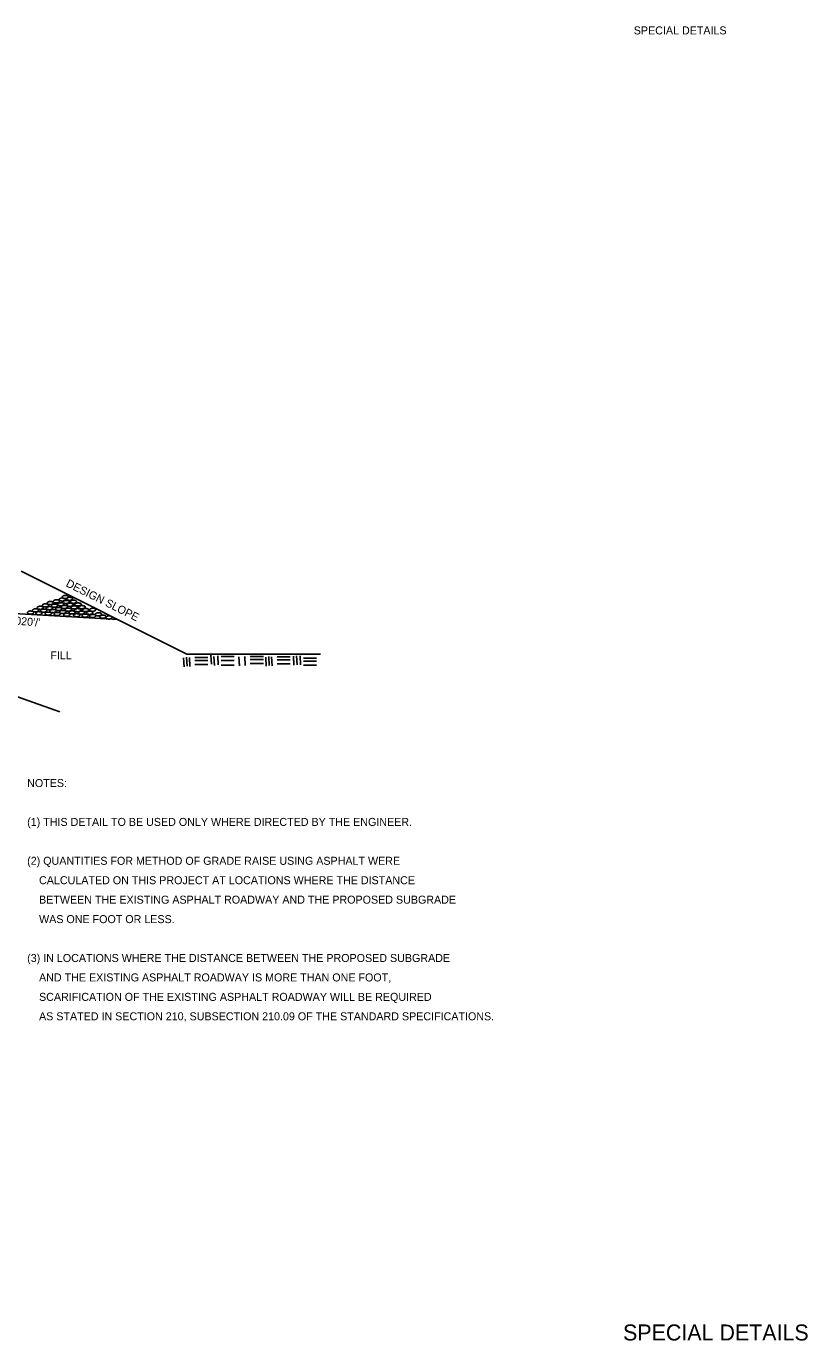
# Model space of a CAD drawing. Extents: x -2842 to 2681, y -2139 to 474.
# Drawn here: x 2096 to 2681, y -512 to 474 of the extents above; entities that cross this region are included whole.
import ezdxf

# ---------------------------------------------------------------- set-up
doc = ezdxf.new("R2010")
doc.units = 0
for name, color, linetype in [('R_Border', 7, 'Continuous'), ('R_Border Prem', 7, 'Continuous'), ('R_Grid', 7, 'Continuous')]:
    doc.layers.add(name, color=color, linetype=linetype)

msp = doc.modelspace()

# ---------------------------------------------------------------- linework, layer by layer
at = {"layer": 'R_Grid'}
for p, q in [((2215.91, 3.06), (2091.72, 65.14)), ((2010.36, 37.94), (2164.16, 28.93)), ((1946.93, 21.56), (2120.76, -40.3)), ((2213.37, 0.4), (2213.76, -6.38)), ((2215.7, 0.85), (2216.09, -5.92)), ((2315.99, 3.06), (2215.91, 3.06)), ((2217.73, 0.63), (2218.1, -6.14)), ((2231.66, 0.63), (2221.87, 0.63)), ((2233.88, 2.35), (2234.23, -4.41)), ((2236.17, 1.2), (2236.54, -5.57)), ((2239.05, 1.79), (2239.43, -4.99)), ((2251.29, 1.21), (2241.46, 1.21)), ((2254.92, 1.13), (2255.31, -5.64)), ((2259.27, 1.37), (2259.65, -5.39)), ((2273.2, 1.37), (2263.42, 1.37)), ((2274.95, 0.83), (2275.34, -5.93)), ((2277.3, 1.31), (2277.65, -5.47)), ((2279.31, 1.07), (2279.69, -5.71)), ((2293.24, 1.07), (2283.46, 1.07)), ((2295.72, 1.55), (2296.09, -5.21)), ((2298.15, 1.81), (2298.52, -4.95)), ((2300.71, 1.81), (2301.09, -4.95)), ((2313, 0.05), (2303.21, 0.05)), ((2231.66, -1.62), (2221.87, -1.62)), ((2231.66, -4.64), (2221.87, -4.64)), ((2251.29, -1.69), (2241.46, -1.69)), ((2251.29, -5.14), (2241.46, -5.14)), ((2273.2, -0.89), (2263.42, -0.89)), ((2273.2, -3.91), (2263.42, -3.91)), ((2293.24, -1.17), (2283.46, -1.17)), ((2293.24, -4.19), (2283.46, -4.19)), ((2313, -2.18), (2303.21, -2.18)), ((2313, -5.22), (2303.21, -5.22))]:
    msp.add_line(p, q, dxfattribs=at)
for points in [[(2109.9, 38.41), (2109.04, 38.49), (2108.06, 38.76), (2107.54, 39.21), (2107.48, 39.51), (2107.71, 40), (2108.04, 40.24), (2108.61, 40.59), (2109.4, 40.74), (2109.79, 40.74), (2110.41, 40.71), (2111.11, 40.64), (2111.64, 40.44), (2112.12, 39.96), (2112.18, 39.68), (2112.03, 39.2), (2111.65, 38.91), (2111.31, 38.72), (2110.78, 38.55), (2110.44, 38.46), (2109.9, 38.41)], [(2113.47, 40.14), (2112.65, 40.23), (2111.65, 40.56), (2111.18, 40.98), (2111.09, 41.28), (2111.35, 41.78), (2111.63, 42.04), (2112.16, 42.32), (2112.94, 42.51), (2113.38, 42.51), (2114, 42.54), (2114.69, 42.4), (2115.25, 42.15), (2115.73, 41.74), (2115.8, 41.42), (2115.68, 40.95), (2115.29, 40.63), (2114.93, 40.51), (2114.33, 40.31), (2114, 40.19), (2113.47, 40.14)], [(2116.69, 38.19), (2115.86, 38.28), (2114.9, 38.55), (2114.39, 39.03), (2114.3, 39.27), (2114.57, 39.83), (2114.87, 40.06), (2115.37, 40.38), (2116.18, 40.56), (2116.6, 40.56), (2117.23, 40.58), (2117.93, 40.47), (2118.46, 40.19), (2118.96, 39.8), (2119.02, 39.47), (2118.89, 39.01), (2118.51, 38.67), (2118.12, 38.51), (2117.56, 38.36), (2117.23, 38.24), (2116.69, 38.19)], [(2118.08, 41.42), (2117.23, 41.51), (2116.24, 41.8), (2115.73, 42.25), (2115.68, 42.56), (2115.93, 43.06), (2116.21, 43.3), (2116.75, 43.58), (2117.56, 43.77), (2117.98, 43.77), (2118.61, 43.74), (2119.31, 43.7), (2119.82, 43.47), (2120.3, 43.02), (2120.38, 42.72), (2120.22, 42.23), (2119.84, 41.95), (2119.48, 41.79), (2118.94, 41.56), (2118.61, 41.43), (2118.08, 41.42)], [(2121.42, 39.22), (2120.57, 39.33), (2119.56, 39.62), (2119.04, 40.06), (2118.98, 40.36), (2119.26, 40.85), (2119.52, 41.1), (2120.13, 41.41), (2120.91, 41.59), (2121.3, 41.59), (2121.93, 41.56), (2122.61, 41.48), (2123.17, 41.28), (2123.62, 40.81), (2123.71, 40.54), (2123.55, 40.04), (2123.19, 39.78), (2122.82, 39.58), (2122.3, 39.4), (2121.96, 39.29), (2121.42, 39.22)], [(2122.47, 42.84), (2121.64, 42.93), (2120.64, 43.2), (2120.16, 43.66), (2120.1, 43.95), (2120.35, 44.44), (2120.62, 44.68), (2121.17, 45), (2121.96, 45.19), (2122.39, 45.19), (2123, 45.13), (2123.71, 45.09), (2124.23, 44.88), (2124.71, 44.42), (2124.79, 44.13), (2124.64, 43.65), (2124.27, 43.37), (2123.9, 43.17), (2123.33, 42.95), (2123, 42.85), (2122.47, 42.84)], [(2124.07, 37.26), (2123.24, 37.35), (2122.27, 37.64), (2121.77, 38.09), (2121.72, 38.38), (2121.96, 38.89), (2122.19, 39.12), (2122.78, 39.4), (2123.56, 39.62), (2123.97, 39.62), (2124.6, 39.58), (2125.3, 39.52), (2125.83, 39.25), (2126.35, 38.84), (2126.41, 38.51), (2126.27, 38.06), (2125.9, 37.76), (2125.52, 37.62), (2124.95, 37.39), (2124.6, 37.27), (2124.07, 37.26)], [(2124.71, 44.7), (2123.88, 44.8), (2122.91, 45.05), (2122.43, 45.55), (2122.35, 45.81), (2122.6, 46.32), (2122.83, 46.55), (2123.41, 46.85), (2124.2, 47.05), (2124.62, 47.05), (2125.25, 47.02), (2125.94, 46.97), (2126.46, 46.7), (2126.99, 46.3), (2127.07, 45.94), (2126.92, 45.52), (2126.54, 45.19), (2126.16, 45.05), (2125.59, 44.84), (2125.25, 44.71), (2124.71, 44.7)], [(2125.42, 40.97), (2124.56, 41.06), (2123.58, 41.32), (2123.07, 41.8), (2123, 42.07), (2123.25, 42.6), (2123.54, 42.81), (2124.09, 43.1), (2124.89, 43.33), (2125.32, 43.33), (2125.94, 43.27), (2126.63, 43.23), (2127.14, 42.95), (2127.64, 42.56), (2127.73, 42.2), (2127.56, 41.78), (2127.18, 41.44), (2126.82, 41.31), (2126.28, 41.1), (2125.94, 40.98), (2125.42, 40.97)], [(2127.88, 43.35), (2127.07, 43.45), (2126.06, 43.69), (2125.57, 44.18), (2125.5, 44.43), (2125.76, 44.97), (2126.04, 45.17), (2126.59, 45.48), (2127.38, 45.7), (2127.78, 45.7), (2128.43, 45.64), (2129.12, 45.6), (2129.66, 45.34), (2130.14, 44.92), (2130.23, 44.58), (2130.06, 44.17), (2129.71, 43.82), (2129.3, 43.66), (2128.76, 43.48), (2128.43, 43.37), (2127.88, 43.35)], [(2128.21, 38.84), (2127.37, 38.96), (2126.38, 39.2), (2125.9, 39.69), (2125.82, 39.95), (2126.07, 40.49), (2126.36, 40.68), (2126.92, 41.01), (2127.71, 41.23), (2128.12, 41.23), (2128.74, 41.16), (2129.44, 41.12), (2129.96, 40.86), (2130.47, 40.45), (2130.54, 40.1), (2130.39, 39.68), (2130, 39.36), (2129.64, 39.17), (2129.08, 39.01), (2128.74, 38.87), (2128.21, 38.84)], [(2130.89, 41.14), (2130.01, 41.23), (2129.05, 41.45), (2128.52, 41.96), (2128.46, 42.22), (2128.72, 42.74), (2129.01, 42.95), (2129.57, 43.28), (2130.37, 43.48), (2130.77, 43.48), (2131.41, 43.45), (2132.09, 43.4), (2132.63, 43.13), (2133.09, 42.72), (2133.18, 42.38), (2133.02, 41.94), (2132.66, 41.62), (2132.28, 41.44), (2131.74, 41.28), (2131.41, 41.16), (2130.89, 41.14)], [(2134.18, 41.56), (2135, 41.45), (2135.99, 41.23), (2136.53, 40.73), (2136.59, 40.48), (2136.36, 39.94), (2136.06, 39.75), (2135.47, 39.38), (2134.69, 39.2), (2134.28, 39.2), (2133.67, 39.25), (2132.95, 39.3), (2132.43, 39.55), (2131.96, 39.97), (2131.9, 40.31), (2132.05, 40.74), (2132.38, 41.07), (2132.76, 41.26), (2133.31, 41.41), (2133.65, 41.54), (2134.18, 41.56)], [(2137.19, 39.46), (2138.04, 39.37), (2139.03, 39.12), (2139.55, 38.62), (2139.62, 38.37), (2139.36, 37.84), (2139.08, 37.64), (2138.49, 37.28), (2137.73, 37.1), (2137.29, 37.1), (2136.66, 37.14), (2135.94, 37.19), (2135.45, 37.46), (2134.96, 37.86), (2134.9, 38.22), (2135.06, 38.65), (2135.41, 38.98), (2135.77, 39.13), (2136.34, 39.3), (2136.65, 39.44), (2137.19, 39.46)], [(2098.71, 33.05), (2097.88, 33.12), (2096.92, 33.37), (2096.44, 33.87), (2096.35, 34.13), (2096.63, 34.67), (2096.86, 34.88), (2097.43, 35.2), (2098.23, 35.4), (2098.62, 35.4), (2099.27, 35.36), (2099.97, 35.3), (2100.52, 35.05), (2100.99, 34.64), (2101.07, 34.3), (2100.91, 33.85), (2100.57, 33.54), (2100.14, 33.35), (2099.6, 33.17), (2099.27, 33.07), (2098.71, 33.05)], [(2102.4, 34.67), (2101.55, 34.73), (2100.61, 35.01), (2100.1, 35.47), (2100.03, 35.76), (2100.29, 36.27), (2100.56, 36.5), (2101.11, 36.81), (2101.88, 37.01), (2102.3, 37.01), (2102.96, 36.97), (2103.66, 36.93), (2104.16, 36.67), (2104.67, 36.25), (2104.75, 35.92), (2104.59, 35.46), (2104.24, 35.17), (2103.82, 34.99), (2103.26, 34.77), (2102.96, 34.67), (2102.4, 34.67)], [(2104.96, 32.56), (2104.09, 32.64), (2103.11, 32.91), (2102.63, 33.37), (2102.55, 33.67), (2102.85, 34.18), (2103.05, 34.42), (2103.66, 34.7), (2104.43, 34.9), (2104.84, 34.9), (2105.47, 34.86), (2106.16, 34.81), (2106.7, 34.58), (2107.21, 34.13), (2107.29, 33.83), (2107.12, 33.34), (2106.75, 33.08), (2106.38, 32.9), (2105.8, 32.67), (2105.47, 32.57), (2104.96, 32.56)], [(2105.88, 36.6), (2105.04, 36.7), (2104.08, 36.97), (2103.61, 37.45), (2103.52, 37.72), (2103.76, 38.24), (2103.99, 38.46), (2104.56, 38.75), (2105.37, 38.98), (2105.78, 38.98), (2106.4, 38.93), (2107.1, 38.87), (2107.63, 38.61), (2108.15, 38.2), (2108.22, 37.86), (2108.08, 37.42), (2107.68, 37.1), (2107.33, 36.95), (2106.75, 36.74), (2106.4, 36.62), (2105.88, 36.6)], [(2108.49, 34.48), (2107.64, 34.56), (2106.7, 34.81), (2106.2, 35.3), (2106.12, 35.57), (2106.38, 36.09), (2106.62, 36.3), (2107.19, 36.62), (2108, 36.83), (2108.38, 36.83), (2109.03, 36.79), (2109.71, 36.74), (2110.25, 36.48), (2110.76, 36.05), (2110.85, 35.73), (2110.68, 35.28), (2110.3, 34.97), (2109.93, 34.79), (2109.39, 34.61), (2109.03, 34.49), (2108.49, 34.48)], [(2112.04, 32.27), (2111.2, 32.36), (2110.24, 32.62), (2109.75, 33.11), (2109.68, 33.35), (2109.93, 33.9), (2110.18, 34.1), (2110.74, 34.43), (2111.53, 34.64), (2111.95, 34.64), (2112.59, 34.6), (2113.27, 34.54), (2113.8, 34.28), (2114.3, 33.87), (2114.39, 33.52), (2114.25, 33.08), (2113.85, 32.75), (2113.49, 32.61), (2112.91, 32.41), (2112.59, 32.27), (2112.04, 32.27)], [(2112.89, 36.34), (2112.03, 36.45), (2111.06, 36.71), (2110.58, 37.18), (2110.51, 37.47), (2110.76, 37.97), (2111, 38.22), (2111.58, 38.5), (2112.37, 38.69), (2112.78, 38.69), (2113.42, 38.66), (2114.11, 38.61), (2114.63, 38.38), (2115.14, 37.93), (2115.21, 37.64), (2115.05, 37.14), (2114.69, 36.88), (2114.3, 36.7), (2113.74, 36.48), (2113.42, 36.35), (2112.89, 36.34)], [(2115.65, 34.14), (2114.78, 34.25), (2113.78, 34.54), (2113.27, 34.98), (2113.18, 35.28), (2113.46, 35.78), (2113.74, 36.01), (2114.32, 36.33), (2115.1, 36.51), (2115.52, 36.51), (2116.13, 36.49), (2116.84, 36.42), (2117.37, 36.2), (2117.84, 35.74), (2117.93, 35.44), (2117.76, 34.97), (2117.38, 34.67), (2117.02, 34.5), (2116.5, 34.34), (2116.16, 34.21), (2115.65, 34.14)], [(2118.68, 34.35), (2119.48, 34.34), (2120.49, 33.98), (2120.99, 33.52), (2121.07, 33.24), (2120.82, 32.71), (2120.5, 32.52), (2119.99, 32.24), (2119.15, 32.02), (2118.74, 31.98), (2118.12, 32.03), (2117.45, 32.17), (2116.92, 32.38), (2116.43, 32.75), (2116.36, 33.1), (2116.5, 33.54), (2116.88, 33.85), (2117.24, 34.07), (2117.79, 34.25), (2118.14, 34.34), (2118.68, 34.35)], [(2119.72, 35.72), (2118.89, 35.81), (2117.91, 36.11), (2117.41, 36.55), (2117.33, 36.83), (2117.59, 37.33), (2117.88, 37.62), (2118.39, 37.88), (2119.2, 38.06), (2119.61, 38.06), (2120.23, 38.09), (2120.93, 37.97), (2121.47, 37.73), (2121.97, 37.28), (2122.05, 37.01), (2121.9, 36.51), (2121.52, 36.23), (2121.14, 36.05), (2120.58, 35.89), (2120.23, 35.76), (2119.72, 35.72)], [(2122.81, 35.84), (2123.64, 35.82), (2124.64, 35.47), (2125.14, 35.01), (2125.21, 34.71), (2124.95, 34.21), (2124.65, 33.98), (2124.11, 33.73), (2123.28, 33.5), (2122.88, 33.46), (2122.27, 33.54), (2121.59, 33.66), (2121.05, 33.87), (2120.57, 34.25), (2120.49, 34.58), (2120.64, 35.02), (2121.02, 35.32), (2121.37, 35.57), (2121.93, 35.74), (2122.28, 35.82), (2122.81, 35.84)], [(2125.9, 33.82), (2126.72, 33.72), (2127.71, 33.38), (2128.2, 32.97), (2128.28, 32.67), (2128.01, 32.19), (2127.73, 31.92), (2127.18, 31.61), (2126.38, 31.43), (2125.97, 31.43), (2125.35, 31.42), (2124.65, 31.52), (2124.11, 31.78), (2123.62, 32.21), (2123.55, 32.5), (2123.71, 32.99), (2124.07, 33.29), (2124.46, 33.45), (2125.02, 33.63), (2125.35, 33.75), (2125.9, 33.82)], [(2126.97, 37.55), (2127.78, 37.52), (2128.82, 37.16), (2129.29, 36.71), (2129.37, 36.42), (2129.1, 35.92), (2128.83, 35.69), (2128.28, 35.44), (2127.47, 35.22), (2127.05, 35.19), (2126.42, 35.25), (2125.76, 35.36), (2125.22, 35.53), (2124.72, 35.95), (2124.65, 36.25), (2124.8, 36.72), (2125.19, 37.02), (2125.54, 37.27), (2126.08, 37.45), (2126.43, 37.52), (2126.97, 37.55)], [(2129.85, 35.5), (2130.69, 35.44), (2131.69, 35.14), (2132.2, 34.68), (2132.28, 34.42), (2132.02, 33.9), (2131.74, 33.67), (2131.16, 33.3), (2130.39, 33.17), (2129.96, 33.17), (2129.32, 33.19), (2128.64, 33.25), (2128.12, 33.5), (2127.64, 33.94), (2127.56, 34.25), (2127.73, 34.7), (2128.1, 35.01), (2128.46, 35.19), (2129, 35.36), (2129.31, 35.46), (2129.85, 35.5)], [(2131.41, 39.24), (2132.28, 39.15), (2133.27, 38.89), (2133.78, 38.41), (2133.84, 38.13), (2133.6, 37.65), (2133.31, 37.4), (2132.72, 37.09), (2131.95, 36.9), (2131.52, 36.9), (2130.91, 36.95), (2130.21, 36.98), (2129.69, 37.22), (2129.21, 37.67), (2129.13, 37.97), (2129.28, 38.43), (2129.68, 38.72), (2130.01, 38.91), (2130.57, 39.12), (2130.91, 39.21), (2131.41, 39.24)], [(2133.35, 33.45), (2134.2, 33.34), (2135.18, 33.11), (2135.66, 32.62), (2135.73, 32.35), (2135.46, 31.85), (2135.21, 31.61), (2134.63, 31.32), (2133.84, 31.09), (2133.44, 31.09), (2132.83, 31.13), (2132.13, 31.21), (2131.59, 31.43), (2131.08, 31.88), (2131.01, 32.19), (2131.16, 32.64), (2131.54, 32.95), (2131.92, 33.12), (2132.48, 33.3), (2132.83, 33.41), (2133.35, 33.45)], [(2134, 37.21), (2134.85, 37.14), (2135.85, 36.86), (2136.39, 36.37), (2136.45, 36.09), (2136.18, 35.57), (2135.89, 35.37), (2135.3, 35.11), (2134.5, 34.83), (2134.08, 34.83), (2133.46, 34.9), (2132.78, 34.98), (2132.27, 35.2), (2131.8, 35.61), (2131.72, 35.94), (2131.88, 36.38), (2132.21, 36.7), (2132.56, 36.9), (2133.11, 37.1), (2133.47, 37.18), (2134, 37.21)], [(2136.87, 35.31), (2137.73, 35.23), (2138.71, 34.95), (2139.2, 34.49), (2139.27, 34.2), (2139.03, 33.71), (2138.73, 33.45), (2138.18, 33.17), (2137.38, 32.96), (2136.99, 32.96), (2136.36, 33.02), (2135.66, 33.07), (2135.13, 33.3), (2134.61, 33.73), (2134.55, 34.02), (2134.71, 34.51), (2135.1, 34.79), (2135.46, 34.97), (2135.99, 35.2), (2136.36, 35.3), (2136.87, 35.31)], [(2139.66, 33.12), (2140.52, 33.08), (2141.48, 32.74), (2141.96, 32.28), (2142.04, 31.98), (2141.78, 31.49), (2141.55, 31.28), (2140.98, 31.01), (2140.19, 30.73), (2139.77, 30.73), (2139.15, 30.81), (2138.48, 30.89), (2137.91, 31.09), (2137.39, 31.52), (2137.31, 31.85), (2137.48, 32.3), (2137.84, 32.61), (2138.23, 32.81), (2138.8, 33.03), (2139.15, 33.11), (2139.66, 33.12)], [(2140.04, 37.28), (2140.87, 37.19), (2141.85, 36.94), (2142.37, 36.47), (2142.44, 36.2), (2142.15, 35.67), (2141.87, 35.46), (2141.32, 35.15), (2140.52, 34.93), (2140.11, 34.93), (2139.49, 34.99), (2138.8, 35.04), (2138.26, 35.28), (2137.78, 35.72), (2137.73, 36.03), (2137.84, 36.48), (2138.23, 36.79), (2138.59, 36.97), (2139.15, 37.19), (2139.52, 37.27), (2140.04, 37.28)], [(2142.98, 35.21), (2143.8, 35.15), (2144.82, 34.83), (2145.29, 34.37), (2145.36, 34.07), (2145.12, 33.57), (2144.87, 33.33), (2144.29, 33.1), (2143.51, 32.84), (2143.09, 32.84), (2142.44, 32.9), (2141.78, 33), (2141.23, 33.2), (2140.74, 33.62), (2140.64, 33.96), (2140.82, 34.4), (2141.18, 34.7), (2141.58, 34.89), (2142.1, 35.11), (2142.44, 35.2), (2142.98, 35.21)], [(2145.2, 35.11), (2144.36, 35.2), (2143.38, 35.46), (2142.9, 35.93), (2142.82, 36.21), (2143.09, 36.72), (2143.34, 36.95), (2143.9, 37.24), (2144.67, 37.46), (2145.12, 37.46), (2145.74, 37.42), (2146.43, 37.36), (2146.95, 37.1), (2147.46, 36.68), (2147.53, 36.34), (2147.39, 35.91), (2147.02, 35.59), (2146.64, 35.45), (2146.05, 35.23), (2145.74, 35.11), (2145.2, 35.11)], [(2145.27, 32.79), (2146.09, 32.77), (2147.09, 32.46), (2147.54, 32), (2147.63, 31.75), (2147.38, 31.19), (2147.13, 30.97), (2146.58, 30.67), (2145.77, 30.49), (2145.32, 30.44), (2144.72, 30.52), (2144.04, 30.64), (2143.49, 30.81), (2143, 31.23), (2142.91, 31.52), (2143.09, 31.98), (2143.43, 32.33), (2143.81, 32.55), (2144.39, 32.68), (2144.74, 32.77), (2145.27, 32.79)], [(2149.56, 34.09), (2150.4, 34.02), (2151.38, 33.72), (2151.89, 33.3), (2151.95, 33.05), (2151.69, 32.49), (2151.44, 32.21), (2150.84, 31.96), (2150.07, 31.79), (2149.67, 31.76), (2149.04, 31.76), (2148.32, 31.88), (2147.83, 32.12), (2147.32, 32.52), (2147.24, 32.84), (2147.38, 33.3), (2147.77, 33.65), (2148.13, 33.82), (2148.7, 33.98), (2149.03, 34.02), (2149.56, 34.09)], [(2152.95, 32.33), (2153.79, 32.24), (2154.76, 31.94), (2155.23, 31.49), (2155.32, 31.23), (2155.08, 30.68), (2154.81, 30.44), (2154.23, 30.14), (2153.44, 29.98), (2153.03, 29.98), (2152.4, 29.99), (2151.73, 30.05), (2151.19, 30.32), (2150.67, 30.71), (2150.59, 31.07), (2150.74, 31.51), (2151.13, 31.84), (2151.49, 31.98), (2152.06, 32.17), (2152.43, 32.27), (2152.95, 32.33)], [(2157.51, 29.37), (2156.64, 29.44), (2155.67, 29.71), (2155.19, 30.19), (2155.12, 30.47), (2155.4, 31), (2155.61, 31.21), (2156.2, 31.49), (2157, 31.74), (2157.41, 31.74), (2158.02, 31.69), (2158.72, 31.63), (2159.25, 31.37), (2159.76, 30.96), (2159.81, 30.64), (2159.69, 30.16), (2159.32, 29.87), (2158.95, 29.69), (2158.36, 29.48), (2158.02, 29.38), (2157.51, 29.37)]]:
    msp.add_spline(points, degree=3, dxfattribs=at)

# ---------------------------------------------------------------- texts
at = {"layer": 'R_Border'}
msp.add_text('SPECIAL DETAILS', height=12, dxfattribs=at).set_placement((2542.77, -511.4))
at = {"layer": 'R_Border Prem'}
msp.add_text('SPECIAL DETAILS', height=6, dxfattribs=at).set_placement((2550.8, 467.59))
at = {"layer": 'R_Grid'}
for s, rotation, p in [('DESIGN SLOPE', 333.43495, (2124.67, 54.17)), ("0.020'/'", 355.62317, (2080.34, 25.71))]:
    msp.add_text(s, height=6, rotation=rotation, dxfattribs=at).set_placement(p)
for s, p in [('FILL', (2113.55, -0.84)), ('NOTES:', (2096.17, -96.56)), ('(1) THIS DETAIL TO BE USED ONLY WHERE DIRECTED BY THE ENGINEER.', (2096.17, -125.7)), ('(2) QUANTITIES FOR METHOD OF GRADE RAISE USING ASPHALT WERE', (2096.17, -154.84)), ('    CALCULATED ON THIS PROJECT AT LOCATIONS WHERE THE DISTANCE', (2096.17, -169.41)), ('    BETWEEN THE EXISTING ASPHALT ROADWAY AND THE PROPOSED SUBGRADE', (2096.17, -183.98)), ('    WAS ONE FOOT OR LESS.', (2096.17, -198.56)), ('(3) IN LOCATIONS WHERE THE DISTANCE BETWEEN THE PROPOSED SUBGRADE', (2096.17, -227.7)), ('    AND THE EXISTING ASPHALT ROADWAY IS MORE THAN ONE FOOT,', (2096.17, -242.27)), ('    SCARIFICATION OF THE EXISTING ASPHALT ROADWAY WILL BE REQUIRED', (2096.17, -256.84)), ('    AS STATED IN SECTION 210, SUBSECTION 210.09 OF THE STANDARD SPECIFICATIONS.', (2096.17, -271.41))]:
    msp.add_text(s, height=6, dxfattribs=at).set_placement(p)

doc.saveas('drawing.dxf')
